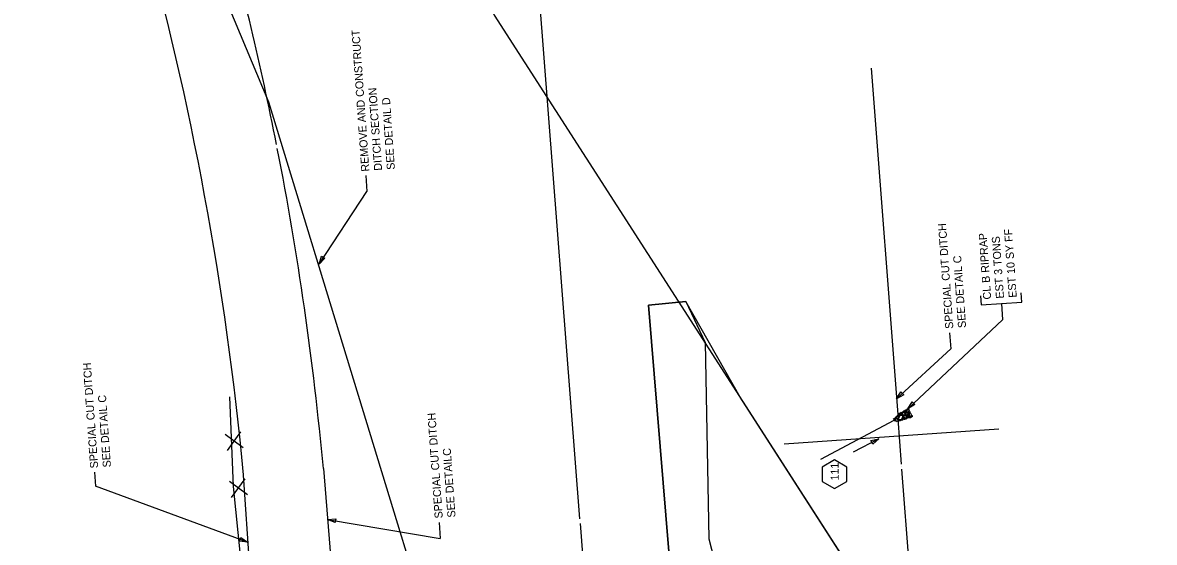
# Model space of a CAD drawing. Extents: x 2384780 to 2405432, y 547869 to 573706.
# Drawn here: x 2399968 to 2400675, y 565776 to 566101 of the extents above; entities that cross this region are included whole.
import ezdxf

# ---------------------------------------------------------------- set-up
doc = ezdxf.new("R2010")
doc.units = 0
for name, color, linetype in [('Old_Level_1', 7, 'Continuous'), ('Old_Level_18', 7, 'Continuous'), ('Old_Level_19', 7, 'Continuous'), ('Old_Level_20', 7, 'Continuous'), ('Old_Level_5', 7, 'Continuous'), ('Old_Level_62', 7, 'Continuous'), ('Old_Level_63', 7, 'Continuous'), ('Prop Drainage Box Number Symbol CELL', 7, 'Continuous')]:
    doc.layers.add(name, color=color, linetype=linetype)

msp = doc.modelspace()

# ---------------------------------------------------------------- linework, layer by layer
at = {"layer": 'Old_Level_1'}
msp.add_line((2400466.75, 565827.98), (2400512.5, 565852.3), dxfattribs=at)
for points in [[(2400512.43, 565853.39), (2400512.62, 565853.23), (2400513.07, 565852.87), (2400512.87, 565852.6), (2400512.71, 565852.5), (2400512.23, 565852.89), (2400512.17, 565853.24), (2400512.43, 565853.39)], [(2400514.01, 565853.85), (2400513.83, 565853.54), (2400513.42, 565853.06), (2400512.88, 565853.17), (2400512.69, 565853.52), (2400513.39, 565854.12), (2400513.75, 565854.09), (2400514.01, 565853.85)], [(2400514.45, 565851.46), (2400514.1, 565851.73), (2400513.37, 565852.45), (2400513.54, 565853.14), (2400514.04, 565853.36), (2400514.86, 565852.44), (2400514.87, 565851.8), (2400514.56, 565851.52)], [(2400514.66, 565852.97), (2400514.32, 565853.35), (2400513.84, 565854.24), (2400514.27, 565854.87), (2400514.73, 565854.89), (2400515.25, 565853.77), (2400515.07, 565853.21), (2400514.66, 565852.97)], [(2400515.39, 565855.64), (2400515.35, 565855.35), (2400514.96, 565855.03), (2400514.66, 565855.11), (2400514.6, 565855.29), (2400515.01, 565855.73), (2400515.21, 565855.76), (2400515.39, 565855.64)], [(2400515.78, 565855.19), (2400515.68, 565854.89), (2400515.29, 565854.61), (2400515, 565854.65), (2400514.9, 565854.85), (2400515.37, 565855.32), (2400515.59, 565855.31), (2400515.78, 565855.19)], [(2400515.8, 565854.6), (2400515.75, 565854.32), (2400515.37, 565854), (2400515.06, 565854.07), (2400515.01, 565854.25), (2400515.42, 565854.7), (2400515.62, 565854.72), (2400515.8, 565854.6)], [(2400517.84, 565855.13), (2400517.74, 565854.28), (2400516.99, 565852.71), (2400515.78, 565852.65), (2400515.2, 565853.24), (2400516.08, 565855.21), (2400516.99, 565855.57), (2400517.9, 565855.29)], [(2400515.79, 565855.23), (2400515.5, 565855.53), (2400515.21, 565856.05), (2400515.56, 565856.5), (2400515.9, 565856.51), (2400516.23, 565855.71), (2400516.04, 565855.36), (2400515.79, 565855.23)], [(2400516.91, 565856.79), (2400516.85, 565856.5), (2400516.47, 565856.18), (2400516.17, 565856.26), (2400516.12, 565856.44), (2400516.51, 565856.88), (2400516.71, 565856.9), (2400516.91, 565856.79)], [(2400517.53, 565856.25), (2400517.45, 565855.99), (2400517.07, 565855.69), (2400516.77, 565855.75), (2400516.67, 565855.95), (2400517.12, 565856.38), (2400517.34, 565856.36), (2400517.53, 565856.25)], [(2400516.92, 565857.37), (2400517.17, 565857.29), (2400517.47, 565856.98), (2400517.44, 565856.63), (2400517.16, 565856.47), (2400516.81, 565856.96), (2400516.76, 565857.27), (2400516.92, 565857.37)], [(2400517.61, 565852.3), (2400517.39, 565852.52), (2400517.12, 565852.93), (2400517.37, 565853.19), (2400517.64, 565853.25), (2400517.87, 565852.66), (2400517.79, 565852.36), (2400517.61, 565852.3)], [(2400518.32, 565852.8), (2400517.99, 565852.96), (2400517.49, 565853.46), (2400517.6, 565853.9), (2400517.87, 565854.03), (2400518.53, 565853.46), (2400518.54, 565853.03), (2400518.32, 565852.8)], [(2400518.05, 565857.5), (2400518.51, 565857.22), (2400519.43, 565856.47), (2400519.1, 565855.57), (2400518.67, 565855.33), (2400517.63, 565856.38), (2400517.54, 565857.14), (2400517.98, 565857.61)], [(2400518.08, 565854.95), (2400517.84, 565855.16), (2400517.74, 565855.57), (2400517.94, 565855.9), (2400518.16, 565855.89), (2400518.45, 565855.36), (2400518.25, 565855.03), (2400518.08, 565854.95)], [(2400518.6, 565854.65), (2400518.56, 565854.38), (2400518.16, 565854.07), (2400517.88, 565854.12), (2400517.77, 565854.32), (2400518.2, 565854.78), (2400518.45, 565854.78), (2400518.6, 565854.65)], [(2400518.93, 565858.12), (2400518.88, 565857.83), (2400518.5, 565857.51), (2400518.19, 565857.58), (2400518.14, 565857.76), (2400518.53, 565858.2), (2400518.73, 565858.23), (2400518.93, 565858.12)], [(2400518.55, 565854.21), (2400518.74, 565854.08), (2400519.16, 565853.74), (2400518.96, 565853.41), (2400518.81, 565853.34), (2400518.33, 565853.77), (2400518.33, 565853.98), (2400518.55, 565854.21)], [(2400519.44, 565853.38), (2400519.39, 565853.1), (2400519.01, 565852.77), (2400518.71, 565852.86), (2400518.62, 565853.03), (2400519.04, 565853.51), (2400519.29, 565853.51), (2400519.44, 565853.38)], [(2400519.39, 565853.54), (2400519.05, 565853.95), (2400518.65, 565854.89), (2400519.04, 565855.44), (2400519.58, 565855.54), (2400520.06, 565854.43), (2400519.88, 565853.73), (2400519.39, 565853.54)], [(2400519.16, 565856.98), (2400518.91, 565857.19), (2400518.81, 565857.6), (2400519.02, 565857.93), (2400519.24, 565857.92), (2400519.53, 565857.39), (2400519.33, 565857.06), (2400519.16, 565856.98)], [(2400519.33, 565858.68), (2400519.65, 565858.55), (2400519.92, 565858.2), (2400519.9, 565857.88), (2400519.63, 565857.73), (2400519.28, 565858.22), (2400519.2, 565858.52), (2400519.33, 565858.68)], [(2400520.07, 565857.21), (2400520.01, 565856.97), (2400519.61, 565856.56), (2400519.31, 565856.66), (2400519.26, 565856.85), (2400519.67, 565857.33), (2400519.87, 565857.36), (2400520.07, 565857.21)], [(2400519.39, 565855.99), (2400519.66, 565856.34), (2400520.41, 565857.09), (2400521.06, 565856.89), (2400521.32, 565856.43), (2400520.39, 565855.63), (2400519.78, 565855.47), (2400519.48, 565855.9)], [(2400520.44, 565853.68), (2400520.38, 565853.4), (2400520.01, 565853.07), (2400519.7, 565853.17), (2400519.62, 565853.33), (2400520.03, 565853.81), (2400520.28, 565853.82), (2400520.44, 565853.68)], [(2400520.75, 565855.43), (2400520.67, 565855.12), (2400520.28, 565854.8), (2400519.98, 565854.9), (2400519.92, 565855.08), (2400520.33, 565855.51), (2400520.56, 565855.55), (2400520.75, 565855.43)], [(2400520.34, 565858.32), (2400520.11, 565858.53), (2400520.01, 565858.95), (2400520.22, 565859.27), (2400520.44, 565859.25), (2400520.72, 565858.72), (2400520.51, 565858.4), (2400520.34, 565858.32)], [(2400520.15, 565857.8), (2400520.36, 565858.26), (2400521.08, 565858.99), (2400521.77, 565858.81), (2400521.91, 565858.3), (2400521.01, 565857.45), (2400520.53, 565857.41), (2400520.08, 565857.76)], [(2400520.3, 565854.61), (2400520.46, 565854.46), (2400520.78, 565854.07), (2400520.7, 565853.78), (2400520.57, 565853.7), (2400520.14, 565854.02), (2400520.1, 565854.34), (2400520.21, 565854.53)], [(2400521.35, 565854.96), (2400521.22, 565854.81), (2400520.89, 565854.39), (2400520.54, 565854.55), (2400520.45, 565854.72), (2400520.91, 565855.22), (2400521.15, 565855.11), (2400521.35, 565854.96)], [(2400521.61, 565857.44), (2400521.55, 565857.15), (2400521.18, 565856.81), (2400520.87, 565856.9), (2400520.79, 565857.07), (2400521.21, 565857.56), (2400521.46, 565857.57), (2400521.61, 565857.44)], [(2400521.66, 565854.31), (2400521.52, 565854.02), (2400521.15, 565853.66), (2400520.88, 565853.77), (2400520.8, 565853.93), (2400521.22, 565854.43), (2400521.47, 565854.43), (2400521.66, 565854.31)], [(2400521.66, 565859.55), (2400521.62, 565859.25), (2400521.24, 565858.93), (2400520.93, 565859.01), (2400520.87, 565859.2), (2400521.27, 565859.64), (2400521.47, 565859.66), (2400521.66, 565859.55)], [(2400521.29, 565856.25), (2400521.62, 565856.03), (2400522.06, 565855.46), (2400521.94, 565855.06), (2400521.67, 565854.92), (2400521.09, 565855.54), (2400521, 565855.92), (2400521.29, 565856.25)], [(2400522.04, 565856.66), (2400521.81, 565856.95), (2400521.5, 565857.51), (2400521.87, 565857.94), (2400522.16, 565858), (2400522.51, 565857.13), (2400522.36, 565856.78), (2400522.04, 565856.66)], [(2400522.07, 565853.89), (2400521.85, 565854.11), (2400521.58, 565854.52), (2400521.83, 565854.78), (2400522.09, 565854.84), (2400522.33, 565854.25), (2400522.24, 565853.95), (2400522.07, 565853.89)], [(2400522.62, 565854.75), (2400522.3, 565855.16), (2400521.81, 565856.01), (2400522.27, 565856.65), (2400522.8, 565856.69), (2400523.3, 565855.6), (2400523.08, 565855), (2400522.62, 565854.75)], [(2400522.76, 565853.9), (2400522.54, 565854.12), (2400522.28, 565854.53), (2400522.53, 565854.79), (2400522.79, 565854.85), (2400523.02, 565854.26), (2400522.94, 565853.96), (2400522.76, 565853.9)], [(2400523.57, 565854.5), (2400523.36, 565854.72), (2400523.09, 565855.14), (2400523.34, 565855.39), (2400523.6, 565855.45), (2400523.84, 565854.86), (2400523.75, 565854.56), (2400523.57, 565854.5)], [(2400513.03, 565852.56), (2400513.19, 565852.4), (2400513.63, 565852.08), (2400513.47, 565851.77), (2400513.3, 565851.68), (2400512.77, 565852.08), (2400512.76, 565852.42), (2400513.03, 565852.56)], [(2400515.09, 565852.18), (2400514.98, 565852.38), (2400514.76, 565852.77), (2400514.97, 565853.02), (2400515.14, 565853.11), (2400515.42, 565852.58), (2400515.37, 565852.22), (2400515.09, 565852.18)], [(2400516.06, 565852.51), (2400516.01, 565852.23), (2400515.63, 565851.9), (2400515.33, 565852), (2400515.24, 565852.16), (2400515.66, 565852.63), (2400515.91, 565852.65), (2400516.06, 565852.51)], [(2400516.78, 565852.53), (2400516.67, 565852.25), (2400516.3, 565851.92), (2400516.01, 565851.98), (2400515.91, 565852.18), (2400516.37, 565852.65), (2400516.6, 565852.65), (2400516.78, 565852.53)]]:
    msp.add_lwpolyline(points, dxfattribs=at)
at = {"layer": 'Old_Level_18'}
for p, q in [((2400498.08, 566072.32), (2400514.94, 565853.21)), ((2400517.13, 565824.84), (2400514.94, 565853.21)), ((2400105.85, 565817.95), (2400115.98, 565669.27)), ((2400156.01, 565822.12), (2400168.29, 565671.35))]:
    msp.add_line(p, q, dxfattribs=at)
msp.add_lwpolyline([(2400517.13, 565823.19), (2400517.11, 565823.35)], dxfattribs=at)
msp.add_arc((2398183.56, 565640.71), 1980.77, 5.25472, 11.10348, dxfattribs=at)
at = {"layer": 'Old_Level_19'}
for p, q in [((2400316.16, 565790.8), (2400253, 566610.89)), ((2400536.47, 565573.8), (2400517.37, 565821.71))]:
    msp.add_line(p, q, dxfattribs=at)
msp.add_lwpolyline([(2400316.39, 565787.76), (2400325.01, 565675.82), (2400335.45, 565540.33), (2400346.22, 565400.39), (2400358.59, 565239.79), (2400367.12, 565129.03)], dxfattribs=at)
for centre, radius, start, end in [((2398139.82, 565633.35), 1975, 5.37234, 15.59355), ((2398183.56, 565640.71), 1980.77, 11.17331, 15.50611)]:
    msp.add_arc(centre, radius, start, end, dxfattribs=at)
at = {"layer": 'Old_Level_20'}
msp.add_lwpolyline([(2400566.39, 565930.16), (2400566.79, 565924.41), (2400592.29, 565926.19), (2400591.89, 565931.94)], dxfattribs=at)
at = {"layer": 'Old_Level_5'}
for p, q in [((2400182.44, 566005.17), (2400183.13, 565995.19)), ((2400153.33, 565949.91), (2400183.13, 565995.19)), ((2400579.54, 565925.3), (2400580.26, 565915.09)), ((2400521.04, 565859.58), (2400580.26, 565915.09)), ((2400547.2, 565906.95), (2400547.89, 565896.97)), ((2400513.97, 565865.82), (2400547.89, 565896.97)), ((2400503, 565840.79), (2400486.85, 565832.51)), ((2400013.04, 565819.85), (2400013.64, 565811.22)), ((2400108.69, 565776.25), (2400013.64, 565811.22)), ((2400158.59, 565790.45), (2400228.97, 565778.56)), ((2400228.28, 565788.54), (2400228.97, 565778.56))]:
    msp.add_line(p, q, dxfattribs=at)
for points in [[(2400156.95, 565953.58), (2400153.33, 565949.91), (2400154.8, 565954.85)], [(2400518.5, 565868.28), (2400513.97, 565865.82), (2400516.81, 565870.12)], [(2400525.54, 565862.09), (2400521.04, 565859.58), (2400523.83, 565863.92)], [(2400497.98, 565839.62), (2400503, 565840.79), (2400499.12, 565837.4)], [(2400163.31, 565788.39), (2400158.59, 565790.45), (2400163.73, 565790.85)], [(2400104.43, 565779.15), (2400108.69, 565776.25), (2400103.57, 565776.8)]]:
    msp.add_lwpolyline(points, close=True, dxfattribs=at)
at = {"layer": 'Old_Level_62'}
msp.add_lwpolyline([(2400440.43, 567218), (2400317.07, 566955.7), (2400169.34, 566748.06), (2400034.82, 566502.63), (2400166.54, 566301.02), (2400262.78, 566105.47), (2400571.01, 565626.1)], dxfattribs=at)
for points in [[(2400339.33, 564522.76), (2400485.81, 564616.68), (2400370.09, 564992.65), (2400258.07, 565392.28), (2400234.01, 565684.68), (2400121.91, 566051.12), (2399969.11, 566416.3), (2399876.99, 566204.34), (2399744.83, 566140.38), (2399726.75, 565925.09), (2400029.82, 565489.59), (2400131.32, 565573.2), (2400194.24, 564735.04)], [(2400409.86, 565308.81), (2400675.07, 565392.61), (2400571.01, 565626.1), (2400416.33, 565866.67), (2400382.41, 565926.44), (2400359.13, 565924.18)], [(2400409.86, 565308.81), (2400359.13, 565924.18), (2400382.41, 565926.44), (2400394.47, 565900.85), (2400396.84, 565778.3), (2400409.44, 565729.12), (2400427.88, 565379.51), (2400429.07, 565329.45), (2400432.37, 565312.82)]]:
    msp.add_lwpolyline(points, close=True, dxfattribs=at)
at = {"layer": 'Old_Level_63'}
for p, q in [((2400443.78, 565837.53), (2400577.95, 565846.91)), ((2400105.94, 565835.04), (2400094.67, 565843.49)), ((2400096.08, 565833.47), (2400104.52, 565845.06)), ((2400108.57, 565805.66), (2400097.3, 565814.11)), ((2400098.71, 565804.09), (2400107.15, 565815.68))]:
    msp.add_line(p, q, dxfattribs=at)
msp.add_lwpolyline([(2400109.17, 565690.88), (2400107.07, 565717.9), (2400104.25, 565767.82), (2400099.93, 565810.9), (2400097.6, 565866.92)], dxfattribs=at)
at = {"layer": 'Prop Drainage Box Number Symbol CELL'}
msp.add_lwpolyline([(2400475.22, 565809.65), (2400482.97, 565814.13), (2400482.97, 565823.08), (2400475.22, 565827.55), (2400467.47, 565823.08), (2400467.47, 565814.13)], close=True, dxfattribs=at)

# ---------------------------------------------------------------- texts
at = {"layer": 'Old_Level_5'}
for s, p in [('REMOVE AND CONSTRUCT', (2400184.76, 566007.84)), ('DITCH SECTION', (2400192.74, 566008.39)), ('SEE DETAIL D', (2400200.72, 566008.95)), ('SPECIAL CUT DITCH', (2400549.52, 565909.61)), ('CL B RIPRAP', (2400573.18, 565927.95)), ('EST 3 TONS', (2400581.16, 565928.51)), ('EST 10 SY FF', (2400589.14, 565929.07)), ('SEE DETAIL C', (2400557.5, 565910.17)), ('SPECIAL CUT DITCH', (2400015.36, 565822.52)), ('SEE DETAIL C', (2400023.34, 565823.08)), ('SPECIAL CUT DITCH', (2400230.6, 565791.2)), ('SEE DETAILC', (2400238.58, 565791.76))]:
    msp.add_text(s, height=5, rotation=93.99991, dxfattribs=at).set_placement(p)
at = {"layer": 'Prop Drainage Box Number Symbol CELL'}
msp.add_text('111', height=5, rotation=90.32242, dxfattribs=at).set_placement((2400477.92, 565814.74))

doc.saveas('drawing.dxf')
